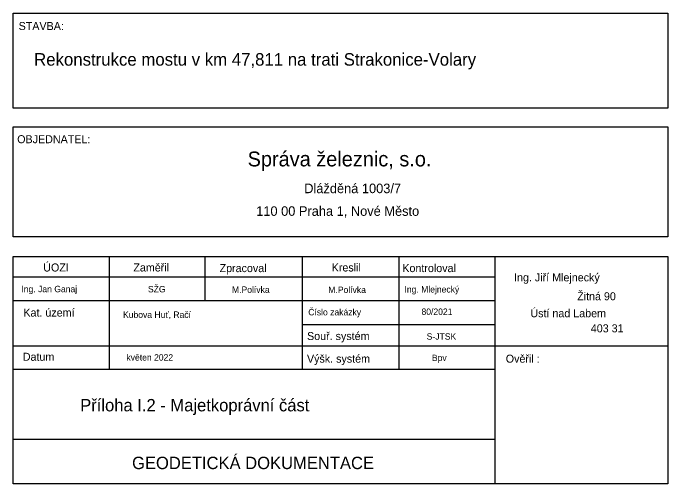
# Model space of a CAD drawing. Extents: x -879530 to -879371, y -1019242 to -1019127.
import ezdxf

# ---------------------------------------------------------------- set-up
doc = ezdxf.new("R2010")
doc.units = 0
doc.layers.add('tabulka', color=7, linetype='Continuous')

msp = doc.modelspace()

# ---------------------------------------------------------------- linework, layer by layer
at = {"layer": 'tabulka'}
for p, q in [((-879530.09, -1019186.45), (-879371.44, -1019186.45)), ((-879506.8, -1019186.45), (-879506.8, -1019213.77)), ((-879483.66, -1019186.45), (-879483.66, -1019197.07)), ((-879460.06, -1019186.45), (-879460.06, -1019213.77)), ((-879436.61, -1019186.45), (-879436.61, -1019213.77)), ((-879413.31, -1019241.58), (-879413.31, -1019186.45)), ((-879530.09, -1019191.36), (-879413.31, -1019191.36)), ((-879530.09, -1019197.07), (-879413.31, -1019197.07)), ((-879460.06, -1019202.88), (-879413.31, -1019202.88)), ((-879530.09, -1019208.07), (-879371.44, -1019208.07)), ((-879530.09, -1019213.77), (-879413.31, -1019213.77)), ((-879530.09, -1019230.76), (-879413.31, -1019230.76))]:
    msp.add_line(p, q, dxfattribs=at)
for points in [[(-879530.09, -1019127.36), (-879371.44, -1019127.36), (-879371.44, -1019150.43), (-879530.09, -1019150.43)], [(-879530.09, -1019154.95), (-879371.44, -1019154.95), (-879371.44, -1019181.64), (-879530.09, -1019181.64)]]:
    msp.add_lwpolyline(points, close=True, dxfattribs=at)
msp.add_lwpolyline([(-879371.44, -1019186.45), (-879371.44, -1019241.58), (-879530.09, -1019241.58), (-879530.09, -1019186.45)], dxfattribs=at)

# ---------------------------------------------------------------- texts
for s, height, p in [('STAVBA:', 1.94, (-879528.75, -1019131.47)), ('Rekonstrukce mostu v km 47,811 na trati Strakonice-Volary', 3.04, (-879525, -1019140.12)), ('OBJEDNATEL:', 1.94, (-879529.1, -1019158.93)), ('Správa železnic, s.o.', 3.61, (-879473.27, -1019164.56)), ('Dlážděná 1003/7', 2.32, (-879459.55, -1019171.05)), ('110 00 Praha 1, Nové Město', 2.32, (-879471.19, -1019176.55)), ('ÚOZI', 1.94, (-879522.79, -1019190.05)), ('Zaměřil', 1.94, (-879500.95, -1019190.05)), ('Zpracoval', 1.94, (-879480.06, -1019190.2)), ('Kreslil', 1.94, (-879452.9, -1019190.05)), ('Kontroloval', 1.94, (-879435.78, -1019190.2)), ('Ing. Jiří Mlejnecký', 1.94, (-879408.71, -1019192.45)), ('Ing. Jan Ganaj', 1.552, (-879528.08, -1019195.08)), ('SŽG', 1.552, (-879497.41, -1019195.11)), ('M.Polívka', 1.552, (-879477.05, -1019195.23)), ('M.Polívka', 1.552, (-879453.72, -1019195.27)), ('Ing. Mlejnecký', 1.552, (-879435.26, -1019195.15)), ('Žitná 90', 1.94, (-879393.42, -1019197.03)), ('Kat. území', 1.94, (-879527.6, -1019200.99)), ('Kubova Huť, Račí', 1.552, (-879503.46, -1019201.3)), ('Číslo zakázky', 1.552, (-879458.58, -1019200.7)), ('80/2021', 1.552, (-879431.14, -1019200.58)), ('Ústí nad Labem', 1.94, (-879404.75, -1019201.15)), ('403 31', 1.94, (-879390.12, -1019204.81)), ('Souř. systém', 1.94, (-879458.87, -1019206.68)), ('S-JTSK', 1.552, (-879429.88, -1019206.59)), ('Datum', 1.94, (-879527.74, -1019211.71)), ('květen 2022', 1.552, (-879502.63, -1019211.67)), ('Výšk. systém', 1.94, (-879458.89, -1019212.17)), ('Bpv', 1.552, (-879428.62, -1019211.78)), ('Ověřil :', 1.94, (-879410.72, -1019212.17)), ('Příloha I.2 - Majetkoprávní část', 3, (-879513.83, -1019223.98)), ('GEODETICKÁ DOKUMENTACE ', 3, (-879501.27, -1019237.99))]:
    msp.add_text(s, height=height, dxfattribs=at).set_placement(p)

doc.saveas('drawing.dxf')
